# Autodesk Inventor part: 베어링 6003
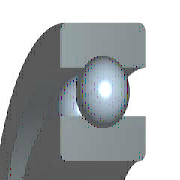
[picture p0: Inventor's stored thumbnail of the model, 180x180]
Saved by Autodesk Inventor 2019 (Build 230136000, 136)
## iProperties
Created: 2012-02
Part Number: 베어링 6003
Material: 강철, 연강
Description: 깊은 그루브 볼 베어링
Document SubType Name: Modeling
Standard: KS B 2023
Designer: mduedu
Standards Organization: KS
Language: ko-KR
Size Designation: 6003 - 17 x 35 x 10
Categories: <MemberInstance><Categories><Category DisplayName="샤프트 부품" InternalName="7f7aeb1f-a693-4053-b835-cee3144e0d98" Mnemonic="SHFT"><Category DisplayName="베어링" Inter
Density: 1 g/cm^3
Appearance: 노란색
IsCustomPart: 1
Author: mduedu
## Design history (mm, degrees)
sketch "스케치" dims "d0" = 4.68 (= -0.26 x WD + 0.26 x BD)
  geometry: L1 (2.66, 13)-(7.34, 13); L2 (5, 13)-(5, 10.66); L3 (5, 13)-(5, 15.34); L4 (3.261, 11.434)-(0, 11.434); L5 (0, 8.5)-(10, 8.5); L6 (3.261, 14.566)-(0, 14.566); L7 (0, 17.5)-(10, 17.5); L8 (10, 8.5)-(10, 11.434); L9 (6.739, 11.434)-(10, 11.434); L10 (6.739, 14.566)-(10, 14.566); L11 (10, 17.5)-(10, 14.566); L12 (-1.4, 0)-(8.4, 0) reference; L13 (0, -0.3)-(0, 5.3) reference
  constraints: 22 end point, 4 point on line, 2 collinear, 2 perpendicular, 2 symmetric about line, 1 midpoint, 1 parallel, 14 other
  dimensions: "d9" = 17 diameter of L5 L12 (= WD); "d11" = 35 diameter of L7 L12 (= BD); "d12" = 10 distance between parallel lines of L8 L13 (= KB); "d13" = 22.868 diameter of L9 L12 (= 0.326 x BD + 0.674 x WD)
revolve "본체" stored, may be unused: angle "d6" = 90 deg
revolve "볼" stored, may be unused: angle "d7" = 90 deg
pattern_circular "IDS_ARRAYBALL[SIMPL:T]" dims angle "d3" = 360 deg
body "Solid1"
fillet "모깎기1" dims "d1" = 0.3 (= KRS)
other parameters: "WD" = 17 [user parameter; used in 5 equation terms], "BD" = 35 [user parameter; used in 5 equation terms], "KB" = 10 [user parameter; used in 1 equation term], "KRS" = 0.3 [user parameter; used in 1 equation term], "d4" = 0, "d5" = 0, "d8" = 0, "d14" = 0, "d15" = 0, "BBA" = 0 [user parameter], "BC0" = 3250000 [user parameter], "BC" = 6050000 [user parameter], "BR" = 17.5 (= 0.5 x BD) [user parameter], "WR" = 8.5 (= 0.5 x WD) [user parameter]
